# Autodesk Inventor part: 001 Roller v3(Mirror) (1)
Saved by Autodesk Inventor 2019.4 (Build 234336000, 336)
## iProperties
Created: 2020-06
Part Number: 001 Roller v3(Mirror) (1)
Material: Generic
Document SubType Name: Modeling
Designer: Administrator
Density: 1 g/cm^3
Appearance: Default
Title: 001 Roller v3(Mirror) (1)
Author: Administrator
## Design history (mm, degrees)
